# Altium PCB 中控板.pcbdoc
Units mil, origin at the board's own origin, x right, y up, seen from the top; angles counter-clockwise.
Board outline 4940 x 2875 mil, 2 copper layers (Top Layer, Bottom Layer); 77 components, 85 nets, 341 pads, 107 vias.
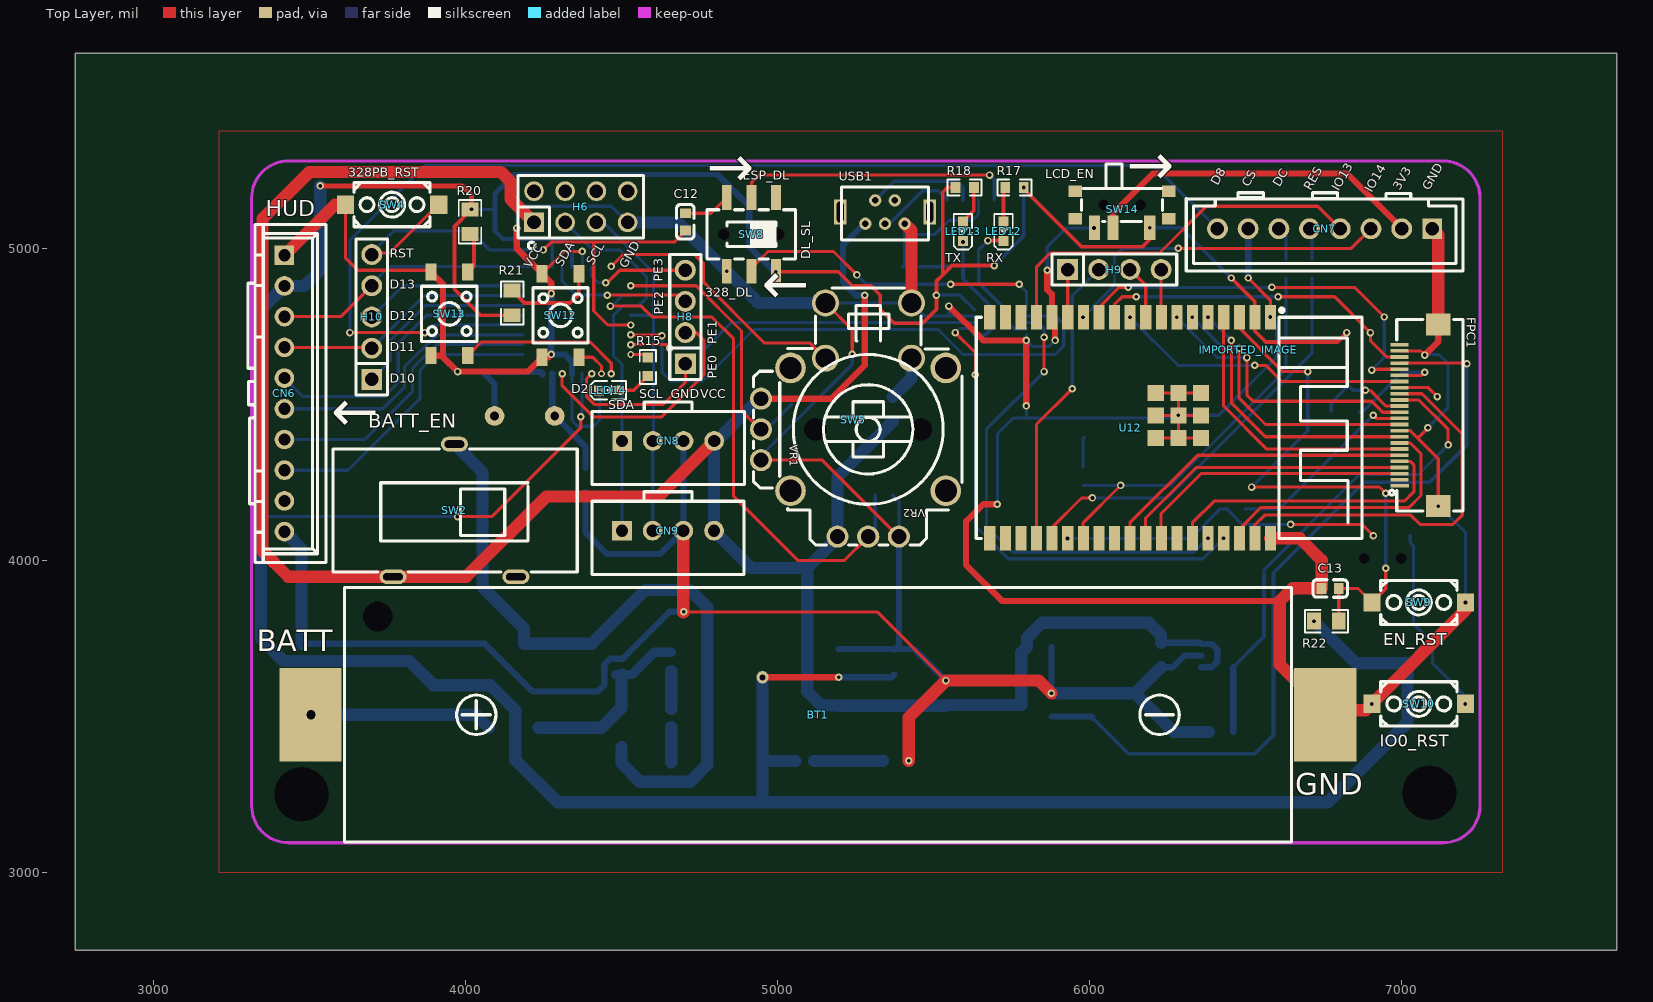
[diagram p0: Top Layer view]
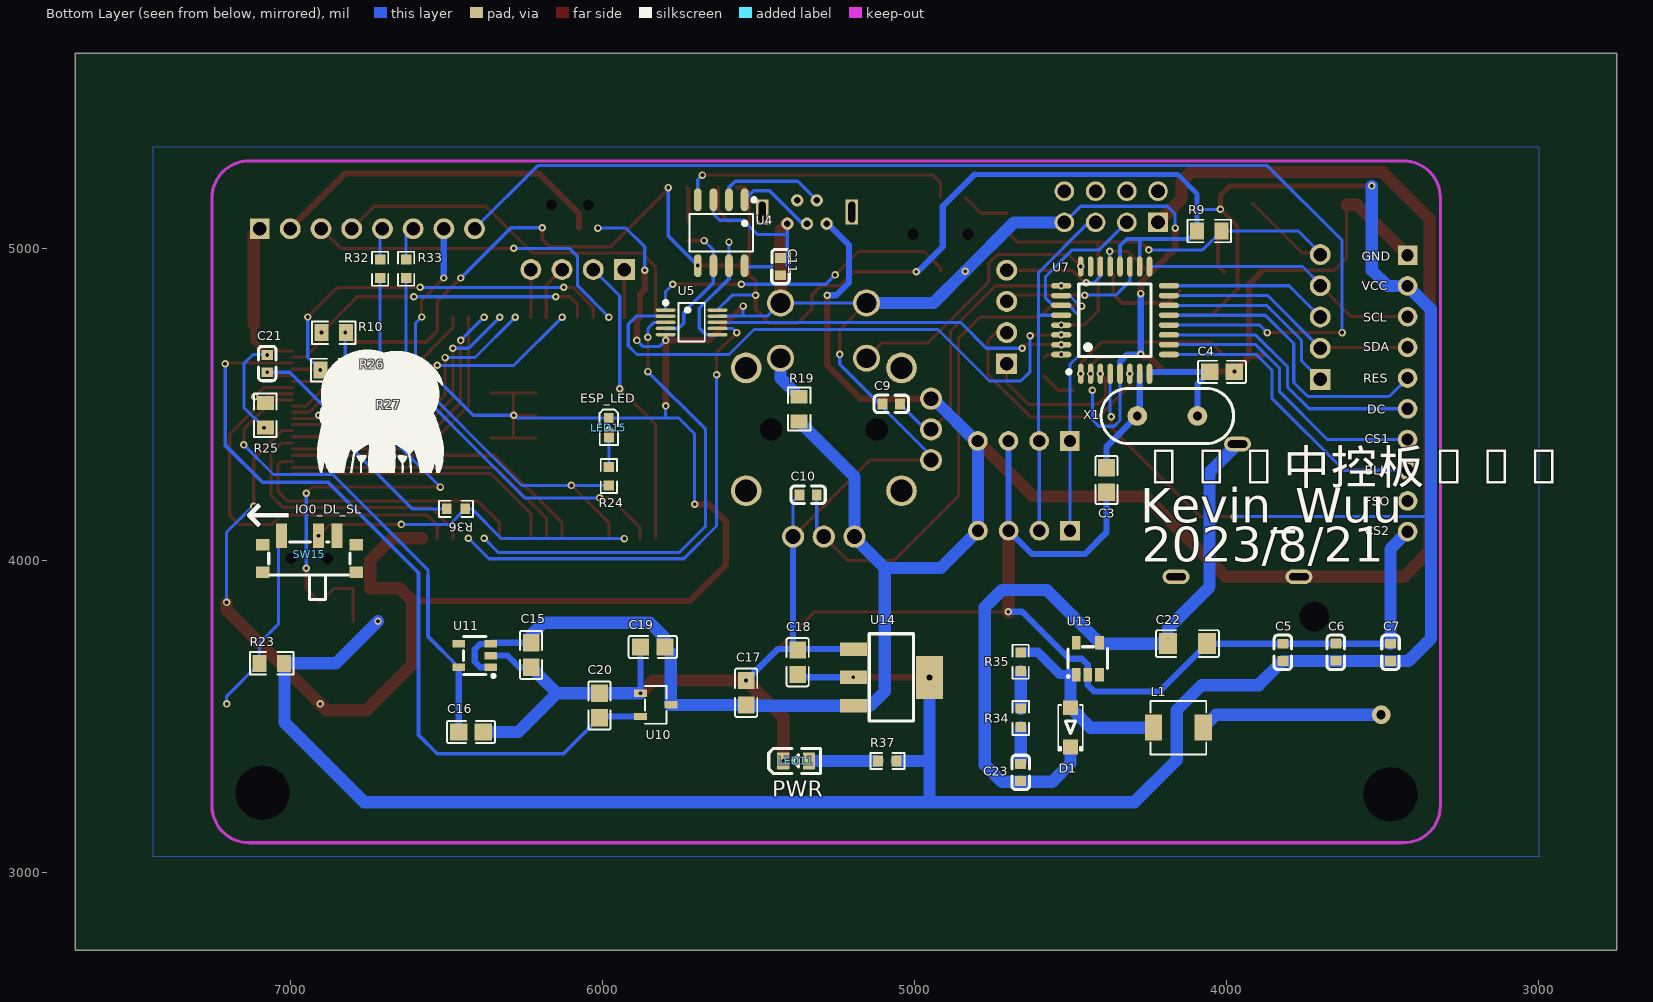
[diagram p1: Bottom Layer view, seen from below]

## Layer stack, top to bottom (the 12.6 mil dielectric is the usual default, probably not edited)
Top Layer: signal copper (thickness not stored)
Dielectric: dielectric 12.6, FR-4, Dk 4.8
Bottom Layer: signal copper (thickness not stored)

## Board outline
7690,2750 2750,2750 2750,5625 7690,5625
cut-out: 7176.61,3255 ccw(c7090,3255) 7003.39,3255 ccw(c7090,3255)
cut-out: 3561.61,3250 ccw(c3475,3250) 3388.39,3250 ccw(c3475,3250)

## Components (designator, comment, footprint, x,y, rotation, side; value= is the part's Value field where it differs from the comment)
BT1 "BH-18650-B1BA002" BATTERY-SMD_18650-1S-L77.1-W20.7-1 5130,3505 r90 top
C3 "0805CG220F500NT" C0805 4385,4257.35 r90 bottom
C4 "0805CG220F500NT" C0805 4015,4604.09 r0 bottom
C5 "CC0603KRX7R9BB104" C0603 3820,3705 r270 bottom
C6 "CC0603KRX7R9BB104" C0603 3650,3705.61 r90 bottom
C7 "CC0603KRX7R9BB104" C0603 3475,3705 r270 bottom
C9 "GRM188R61E106KA73D" C0603 5075,4501.55 r0 bottom
C10 "GRM188R61E106KA73D" C0603 5341.15,4210 r180 bottom
C11 "CC0603KRX7R9BB104" C0603 5430,4941.31 r270 bottom
C12 "CC0603KRX7R9BB104" C0603 4704.89,5085 r270 top
C13 "CC0603KRX7R9BB104" C0603 6771.73,3910 r180 top
C15 "CL21B105KBFNNNE" C0805 6229.37,3696.74 r90 bottom
C16 "CL21B105KBFNNNE" C0805 6421.81,3450 r0 bottom
C17 "CL21B105KBFNNNE" C0805 5540.16,3575.51 r90 bottom
C18 "CL21B105KBFNNNE" C0805 5375.09,3673.46 r90 bottom
C19 "CL21B105KBFNNNE" C0805 5839.26,3722.21 r0 bottom
C20 "CL21B105KBFNNNE" C0805 6010,3534.86 r90 bottom
C21 "CC0603KRX7R9BB104" C0603 7075,4630.56 r270 bottom
C22 "CL31A226KAHNNNE" C1206 4125.57,3733.11 r0 bottom
C23 "CC0603JRNPO9BN121" C0603 4660.11,3320 r270 bottom
CN6 "HC-XHB-10A" CONN-TH_10P-P2.50_HCTL_HC-XHB-10A 3420,4535 r270 top
CN7 "HC-XHB-8A" CONN-TH_8P-P2.50_HCTL_HC-XHB-8A 6755,5062.71 r180 top
CN8 "HX25035-4A" CONN-TH_4P-P2.50_HX25035-4A 4650,4382.78 r0 top
CN9 "HX25035-4A" CONN-TH_4P-P2.50_HX25035-4A 4649.46,4095 r0 top
D1 "MSK240AW" SOD-123FL_L2.8-W1.8-LS3.7-RD 4500.55,3465 r90 bottom
FPC1 "AFC24-S24FIA-00" FPC-SMD_P0.50-24P_QCHF-SM-H2.0 7056.18,4465 r270 top
H6 "DS1023-2*4SF11" HDR-TH_8P-P2.54-V-F-R2-C4-S2.54-1 4370,5133.14 r0 top
H8 "PZ254V-11-04P" HDR-TH_4P-P2.54-V-M 4705,4780 r90 top
H9 "PZ254V-11-04P" HDR-TH_4P-P2.54-V-M 6080,4932.15 r0 top
H10 "HDR-M_2.54_1x5P" HDR-TH_5P-P2.54-V-M 3700,4780 r90 top
IMPORTED_IMAGE "IMPORTED_IMAGE" IMPORTED_IMAGE 6510,4675 r0 top
L1 "MWSA0402S-2R2MT" IND-SMD_L4.4-W4.2 4155,3463.67 r180 bottom
LED11 "NCD0805B2" LED0805-R-RD 5380,3357.38 r180 bottom
LED12 "NCD0603R5" LED0603-RD 5725,5055 r90 top
LED13 "NCD0603R5" LED0603-RD 5595,5055 r90 top
LED14 "NCD0603R5" LED0603-RD 4460,4545 r0 top
LED15 "NCD0603R5" LED0603-RD 5980.21,4425 r270 bottom
R9 "RMCF0805FT10K0" R0805 4055.65,5055.63 r0 bottom
R10 "0805W8F4701T5E" R0805 6861.67,4730 r180 bottom
R15 "0603WAF4700T5E" R0603 4585,4620 r90 top
R17 "0603WAF4700T5E" R0603 5760,5195 r0 top
R18 "0603WAF4700T5E" R0603 5600,5195 r180 top
R19 "RMCF0805FT10K0" R0805 5370,4485 r270 bottom
R20 "RMCF0805FT10K0" R0805 4015,5085.31 r90 top
R21 "RMCF0805FT10K0" R0805 4150,4825 r270 top
R22 "RMCF0805FT10K0" R0805 6759.92,3805 r180 top
R23 "RMCF0805FT10K0" R0805 7060.62,3670 r180 bottom
R24 "0603WAF4700T5E" R0603 5980,4269.89 r270 bottom
R25 "RMCF0805FT10K0" R0805 7080.94,4465 r90 bottom
R26 "0805W8F4701T5E" R0805 6865,4609.94 r180 bottom
R27 "RMCF0805FT10K0" R0805 6814.69,4480 r180 bottom
R32 "0603WAF0000T5E" R0603 6713.34,4934.68 r270 bottom
R33 "0603WAF0000T5E" R0603 6630,4934.68 r270 bottom
R34 "RC0603FR-073RL" R0603 4660,3495 r270 bottom
R35 "0603WAF200KT5E" R0603 4660.11,3675 r270 bottom
R36 "0603WAF0000T5E" R0603 6470,4165 r0 bottom
R37 "0603WAF4700T5E" R0603 5087.52,3356.83 r180 bottom
SW2 "SS12J01 071" SW-TH_SHOU-HAN_SS12J01 3965,4160 r180 top
SW4 "K2-1107ST-A4DW-06_C118141" KEY-SMD_L6.2-W3.6-LS8.0 3765,5140 r180 top
SW5 "RKJXV1224005" SW-TH_RKJXV1224005 5243.81,4450.56 r180 top
SW8 "MS-22D28-G020" SW-SMD_MS-22D28-G020 4916.73,5045 r0 top
SW9 "K2-1107ST-A4DW-06_C118141" KEY-SMD_L6.2-W3.6-LS8.0 7055.82,3865 r0 top
SW10 "K2-1107ST-A4DW-06_C118141" KEY-SMD_L6.2-W3.6-LS8.0 7055.82,3540 r180 top
SW12 "TS-1009S-03826" SW-SMD_4P-L4.5-W4.5-P3.00-LS7.0 4304.81,4785 r270 top
SW13 "TS-1009S-03826" SW-SMD_4P-L4.5-W4.5-P3.00-LS7.0 3948.57,4790 r270 top
SW14 "MK-12C02-G020" SW-SMD_MK-12C02-G020 6105,5125 r180 top
SW15 "MK-12C02-G020" SW-SMD_MK-12C02-G020 6940.05,4020 r180 bottom
U4 "CH340N" SOP-8_L4.9-W3.9-P1.27-LS6.0-BL 5620,5050 r0 bottom
U5 "MSUSB30" MSOP-10_L3.0-W3.0-P0.50-LS5.0-BL 5715,4762.96 r270 bottom
U7 "ATMEGA328PB-AU" TQFP-32_L7.0-W7.0-P0.80-LS9.0-BL 4357.52,4770 r180 bottom
U10 "XC6206-2.8V" SOT-23-3_L2.9-W1.6-P1.90-LS2.8-BR 5830,3536.83 r0 bottom
U11 "RT9013-12GB" SOT-23-5_L3.0-W1.7-P0.95-LS2.8-BR 6410,3694.77 r180 bottom
U12 "ESP32-WROVER-E-N4R8" WIFI-SMD_ESP32-WROVER-E 6130.74,4425 r270 top
U13 "TPS613222ADBVR" TSOT-23-5_L2.9-W1.6-P0.95-LS2.8-BR 4445,3685.07 r270 bottom
U14 "TLV1117LV33DCYR" SOT-223_L6.7-W3.5-P2.30-BR 5074.69,3625 r0 bottom
USB1 "920-462A2021Y10102" MINI-USB-TH_C13453 5345,5116.48 r0 top
X1 "X49SD8MSD2SC" OSC-TH_L10.0-W4.5-P5.00 4190,4462.84 r90 bottom

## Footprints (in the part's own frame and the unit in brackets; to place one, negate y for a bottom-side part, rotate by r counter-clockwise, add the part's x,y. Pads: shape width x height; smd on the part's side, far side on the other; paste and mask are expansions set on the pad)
BATTERY-SMD_18650-1S-L77.1-W20.7-1 [mil]
  rect 300x200 smd mask+2.01: 1(0,-1626.5) 2(0,1626.5)
  Multi-Layer board cut-out: 314.96,1363.78 335.46,1368.45 351.9,1381.56 361.02,1400.51 361.02,1421.53 351.9,1440.48 335.46,1453.59 314.96,1458.26 314.96,1458.26 294.46,1453.59 278.02,1440.48 268.9,1421.53 268.9,1400.51 278.02,1381.56 294.46,1368.45 314.96,1363.78
  silkscreen extent -408,-1518 408,1518
C0603 [mm]
  rect 0.8x0.9 smd mask+0.051: 1(-0.7,0) 2(0.7,0)
  silkscreen extent -1.41,-0.71 1.39,0.72
C0805 [mm]
  rect 1.41x1.35 smd paste-100 mask+0.051: 1(-1,0) 2(1,0)
  silkscreen extent -1.96,-0.9 1.96,0.9
C1206 [mm]
  rect 1.485x1.728 smd paste-100 mask+0.051: 1(-1.593,0) 2(1.593,0)
  silkscreen extent -2.56,-1.09 2.56,1.09
CONN-TH_4P-P2.50_HX25035-4A [mm]
  rect 1.6x1.6 hole 1 mask+0.051: 1(-3.75,0)
  round 1.6 hole 1 mask+0.051: 2(-1.25,0) 3(1.25,0) 4(3.75,0)
  silkscreen extent -6.2,-3.55 6.2,3.17
CONN-TH_8P-P2.50_HCTL_HC-XHB-8A [mm]
  rect 1.6x1.7 hole 1.1 mask+0.051: 1(-8.75,0)
  round 1.7 hole 1.1 mask+0.051: 2(-6.25,0) 3(-3.75,0) 4(-1.25,0) 5(1.25,0) 6(3.75,0) 7(6.25,0)
  round 1.7 hole 1.1 paste+0 mask+0.05: 8(8.75,0)
  silkscreen extent -11.25,-2.94 11.29,3.43
CONN-TH_10P-P2.50_HCTL_HC-XHB-10A [mm]
  rect 1.6x1.6 hole 1 mask+0.051: 1(-11.25,0)
  round 1.6 hole 1 mask+0.051: 2(-8.75,0) 3(-6.25,0) 4(-3.75,0) 5(-1.25,0) 6(1.25,0) 7(3.75,0) 8(6.25,0) 9(8.75,0) 10(11.25,0)
  silkscreen extent -13.75,-2.96 13.75,3.4
FPC-SMD_P0.50-24P_QCHF-SM-H2.0 [mm]
  rect 0.3x1.5 smd mask+0.051: 1(5.75,-1.574) 2(5.252,-1.576) 3(4.752,-1.576) 4(4.252,-1.576) 5(3.752,-1.576) 6(3.252,-1.576) 7(2.752,-1.576) 8(2.252,-1.576) 9(1.752,-1.576) 10(1.252,-1.576) 11(0.752,-1.576) 12(0.252,-1.576) 13(-0.248,-1.576) 14(-0.748,-1.576) 15(-1.248,-1.576) 16(-1.748,-1.576) 17(-2.248,-1.576) 18(-2.748,-1.576) 19(-3.248,-1.576) 20(-3.748,-1.576) 21(-4.248,-1.576) 22(-4.748,-1.576) 23(-5.248,-1.576) 24(-5.748,-1.576)
  rect 1.8x2 smd mask+0.051: 25(7.4,1.576) 26(-7.4,1.576)
  silkscreen extent -7.8,-2.4 7.8,3.6
HDR-TH_4P-P2.54-V-M [mm]
  rect 1.7x1.7 hole 1.1 mask+0.051: 1(-3.81,0)
  round 1.7 hole 1.1 mask+0.051: 2(-1.27,0) 3(1.27,0) 4(3.81,0)
  silkscreen extent -5.08,-1.27 5.08,1.27
HDR-TH_5P-P2.54-V-M [mm]
  rect 1.7x1.7 hole 1.1 mask+0.051: 1(-5.08,0)
  round 1.7 hole 1.1 mask+0.051: 2(-2.54,0) 3(0,0) 4(2.54,0) 5(5.08,0)
  silkscreen extent -6.35,-1.27 6.35,1.27
HDR-TH_8P-P2.54-V-F-R2-C4-S2.54-1 [mm]
  rect 1.6x1.6 hole 1.1 mask+0.051: 1(-3.81,-1.27)
  round 1.6 hole 1.1 mask+0.051: 2(-3.81,1.27) 3(-1.27,-1.27) 4(-1.27,1.27) 5(1.27,-1.27) 6(1.27,1.27) 7(3.81,-1.27) 8(3.81,1.27)
  silkscreen extent -5.1,-3.42 5.1,2.55
IMPORTED_IMAGE [mil]
IND-SMD_L4.4-W4.2 [mm]
  rect 1.4x2.12 smd mask+0.051: 1(2.028,0) 2(-2.028,0)
  silkscreen extent -2.28,-2.18 2.28,2.18
KEY-SMD_L6.2-W3.6-LS8.0 [mm]
  rect 1.4x1.5 smd mask+0.051: 1(-3.8,0) 2(3.8,0)
  silkscreen extent -3.1,-1.8 3.1,1.8
LED0603-RD [mm]
  rect 0.8x0.8 smd mask+0.051: 1(-0.799,-0.003) 2(0.799,0.003)
  silkscreen extent -1.49,-0.75 1.39,0.76
LED0805-R-RD [mm]
  rect 1x1.4 smd mask+0.051: 1(1.05,0) 2(-1.05,0)
  silkscreen extent -2.22,-1.04 1.99,1.01
MINI-USB-TH_C13453 [mm]
  round 1 hole 0.55 mask+0.051: 1(-1.6,-0.95) 2(-0.8,0.95) 3(0,-0.95) 4(0.8,0.95) 5(1.6,-0.95)
  rect 1x2 hole 0.55 slot 1.7 at 90 deg mask+0.051: 6(3.65,0) 7(-3.65,0)
  silkscreen extent -3.56,-2.29 3.56,2.03
MSOP-10_L3.0-W3.0-P0.50-LS5.0-BL [mm]
  oval 0.28x1.62 smd mask+0.051: 1(-1,-2.11) 2(-0.5,-2.11) 3(0,-2.11) 4(0.5,-2.11) 5(1,-2.11) 6(1,2.11) 7(0.5,2.11) 8(0,2.11) 9(-0.5,2.11) 10(-1,2.11)
  silkscreen extent -1.74,-2.26 1.58,1.07
OSC-TH_L10.0-W4.5-P5.00 [mm]
  round 1.6 hole 0.7 mask+0.051: 1(0,2.45) 2(0,-2.45)
  silkscreen extent -2.25,-5.39 2.25,5.39
R0603 [mil]
  rect 31.75x34.02 smd paste-3937.01 mask+2: 1(-29.66,0) 2(29.66,0)
  silkscreen extent -55,-26 55,26
R0805 [mm]
  rect 1.133x1.377 smd paste-100 mask+0.051: 1(-1,0) 2(1,0)
  silkscreen extent -1.76,-0.92 1.76,0.92
SOD-123FL_L2.8-W1.8-LS3.7-RD [mm]
  rect 1.2x1.2 smd mask+0.051: 1(-1.6,0) 2(1.6,0)
  silkscreen extent -1.9,-1 1.8,1
SOP-8_L4.9-W3.9-P1.27-LS6.0-BL [mm]
  oval 0.63x1.865 smd mask+0.051: 1(-1.905,-2.682) 2(-0.635,-2.682) 3(0.635,-2.682) 4(1.905,-2.682) 5(1.905,2.682) 6(0.635,2.682) 7(-0.635,2.682) 8(-1.905,2.682)
  silkscreen extent -2.82,-2.83 2.58,1.52
SOT-23-3_L2.9-W1.6-P1.90-LS2.8-BR [mm]
  rect 1.07x0.6 smd mask+0.051: 1(1.235,-0.95) 2(1.235,0.95) 3(-1.235,0)
  silkscreen extent -0.88,-1.54 0.88,1.54
SOT-23-5_L3.0-W1.7-P0.95-LS2.8-BR [mm]
  rect 1x0.6 smd mask+0.051: 1(1.3,-0.95) 2(1.3,0) 3(1.3,0.95) 4(-1.3,0.95) 5(-1.3,-0.95)
  silkscreen extent -0.9,-1.78 1.65,1.55
SOT-223_L6.7-W3.5-P2.30-BR [mm]
  rect 2.2x1.1 smd mask+0.051: 1(3.099,-2.3) 2(3.099,0) 3(3.099,2.3)
  rect 2.2x3.5 smd mask+0.051: 4(-3.099,0)
  silkscreen extent -1.8,-3.55 1.8,3.55
SW-SMD_4P-L4.5-W4.5-P3.00-LS7.0 [mm]
  rect 1.4x0.9 smd mask+0.051: 1(-3.4,1.5) 2(3.4,1.5) 3(-3.4,-1.5) 4(3.4,-1.5)
  silkscreen extent -2.25,-2.25 2.25,2.25
SW-SMD_MK-12C02-G020 [mm]
  rect 0.9x2 smd mask+0.051: 1(-2.25,1.491) 2(0.75,1.491) 3(2.25,1.491)
  rect 1.1x0.93 smd mask+0.051: 4(3.8,0.779) 5(3.8,-1.491) 6(-3.8,-1.491) 7(-3.8,0.779)
  Multi-Layer board cut-out: 1.075,-0.356 1.117,-0.54 1.235,-0.688 1.405,-0.77 1.595,-0.77 1.765,-0.688 1.883,-0.54 1.925,-0.356 1.925,-0.356 1.883,-0.171 1.765,-0.023 1.595,0.059 1.405,0.059 1.235,-0.023 1.117,-0.171 1.075,-0.356
  Multi-Layer board cut-out: -1.925,-0.356 -1.883,-0.54 -1.765,-0.688 -1.595,-0.77 -1.405,-0.77 -1.235,-0.688 -1.117,-0.54 -1.075,-0.356 -1.075,-0.356 -1.117,-0.171 -1.235,-0.023 -1.405,0.059 -1.595,0.059 -1.765,-0.023 -1.883,-0.171 -1.925,-0.356
  silkscreen extent -3.3,-3.71 3.3,0.99
SW-SMD_MS-22D28-G020 [mm]
  rect 0.8x2 smd mask+0.051: 1(-2,3) 2(0,3) 3(2,3) 4(-2,-3) 5(0,-3) 6(2,-3)
  Multi-Layer board cut-out: -1.8,0 -1.844,0.195 -1.969,0.352 -2.15,0.439 -2.35,0.439 -2.531,0.352 -2.655,0.195 -2.7,0 -2.7,0 -2.655,-0.195 -2.531,-0.352 -2.35,-0.439 -2.15,-0.439 -1.969,-0.352 -1.844,-0.195 -1.8,0
  Multi-Layer board cut-out: 2.7,0 2.655,0.195 2.531,0.352 2.35,0.439 2.15,0.439 1.969,0.352 1.844,0.195 1.8,0 1.8,0 1.844,-0.195 1.969,-0.352 2.15,-0.439 2.35,-0.439 2.531,-0.352 2.655,-0.195 2.7,0
  silkscreen extent -3.6,-2 3.6,2
SW-TH_RKJXV1224005 [mm]
  round 1.8 hole 1.2 mask+0.051: 1(7.527,-1.719) 2(7.527,0.781) 3(7.527,3.281) 4(1.297,9.511) 5(-1.202,9.511) 6(-3.703,9.511)
  round 2.5 hole 1.8 mask+0.051: 7(-7.527,5.781) 8(-7.527,-4.219) 9(5.123,-4.219) 10(5.123,5.781)
  round 2.2 hole 1.6 mask+0.051: a(-4.722,-5.011) b(-4.722,-9.511) c(2.278,-5.011) d(2.278,-9.511)
  Multi-Layer board cut-out: -6.403,0.781 -6.314,0.39 -6.064,0.077 -5.703,-0.097 -5.302,-0.097 -4.942,0.077 -4.692,0.39 -4.603,0.781 -4.603,0.781 -4.692,1.171 -4.942,1.485 -5.302,1.658 -5.703,1.658 -6.064,1.485 -6.314,1.171 -6.403,0.781
  Multi-Layer board cut-out: 2.197,0.781 2.286,0.39 2.536,0.077 2.897,-0.097 3.298,-0.097 3.658,0.077 3.908,0.39 3.997,0.781 3.997,0.781 3.908,1.171 3.658,1.485 3.298,1.658 2.897,1.658 2.536,1.485 2.286,1.171 2.197,0.781
  silkscreen extent -8.85,-10.72 8.15,10.2
SW-TH_SHOU-HAN_SS12J01 [mm]
  oval 2.2x1.2 hole 0.6 slot 1.6 at 0 deg paste+0 mask+0.05: 1(-5,5.4) 2(0,-5.4) 3(5,5.4)
  silkscreen extent -10,-5 9.9,5
TQFP-32_L7.0-W7.0-P0.80-LS9.0-BL [mm]
  oval 0.45x1.65 smd mask+0.051: 1(-2.8,-4.369) 2(-2,-4.369) 3(-1.2,-4.369) 4(-0.4,-4.369) 5(0.4,-4.369) 6(1.2,-4.369) 7(2,-4.369) 8(2.8,-4.369) 17(2.8,4.369) 18(2,4.369) 19(1.2,4.369) 20(0.4,4.369) 21(-0.4,4.369) 22(-1.2,4.369) 23(-2,4.369) 24(-2.8,4.369)
  oval 1.65x0.45 smd mask+0.051: 9(4.381,-2.8) 10(4.381,-2) 11(4.381,-1.2) 12(4.381,-0.4) 13(4.381,0.4) 14(4.381,1.2) 15(4.381,2) 16(4.381,2.8) 25(-4.381,2.8) 26(-4.381,2) 27(-4.381,1.2) 28(-4.381,0.4) 29(-4.381,-0.4) 30(-4.381,-1.2) 31(-4.381,-2) 32(-4.381,-2.8)
  silkscreen extent -3.91,-4.36 2.94,2.95
TSOT-23-5_L2.9-W1.6-P0.95-LS2.8-BR [mm]
  rect 1.1x0.7 smd mask+0.051: 1(1.294,-0.951) 2(1.294,-0.001) 3(1.294,0.951) 4(-1.294,0.951) 5(-1.294,-0.949)
  silkscreen extent -0.97,-1.65 1.52,1.61
WIFI-SMD_ESP32-WROVER-E [mm]
  rect 2x0.9 smd mask+0.051: 1(-9,11.43) 2(-9,10.16) 3(-9,8.89) 4(-9,7.62) 5(-9,6.35) 6(-9,5.08) 7(-9,3.81) 8(-9,2.54) 9(-9,1.27) 10(-9,0) 11(-9,-1.27) 12(-9,-2.54) 13(-9,-3.81) 14(-9,-5.08) 15(-9,-6.35) 16(-9,-7.62) 17(-9,-8.89) 18(-9,-10.16) 19(-9,-11.43) 20(9,-11.43) 21(9,-10.16) 22(9,-8.89) 23(9,-7.62) 24(9,-6.35) 25(9,-5.08) 26(9,-3.81) 27(9,-2.54) 28(9,-1.27) 29(9,0) 30(9,1.27) 31(9,2.54) 32(9,3.81) 33(9,5.08) 34(9,6.35) 35(9,7.62) 36(9,8.89) 37(9,10.16) 38(9,11.43)
  rect 1.33x1.33 smd mask+0.051: 39(-2.835,5.765) 39(-2.835,3.93) 39(-2.835,2.095) 39(-1,5.765) 39(-1,3.93) 39(-1,2.095) 39(0.835,3.93) 39(0.835,2.095) 39(0.835,5.765)
  silkscreen extent -9.72,-12.53 9,18.87

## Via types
v1: diameter 24.02, hole 12.01, Top Layer to Bottom Layer, 100 vias
v2: diameter 21.65, hole 12.01, Top Layer to Bottom Layer, 2 vias
v3: diameter 23.62, hole 12.01, Top Layer to Bottom Layer, 2 vias
v4: diameter 23.23, hole 12.01, Top Layer to Bottom Layer, 1 vias
v5: diameter 59.06, hole 29.53, Top Layer to Bottom Layer, 1 vias
v6: diameter 39.37, hole 19.68, Top Layer to Bottom Layer, 1 vias

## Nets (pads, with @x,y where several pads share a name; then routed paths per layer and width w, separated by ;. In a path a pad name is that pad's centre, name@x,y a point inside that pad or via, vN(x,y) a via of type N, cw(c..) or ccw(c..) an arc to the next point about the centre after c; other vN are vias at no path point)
2.4LCD_DC: CN7.6 R33.1 | length 107.7
  Bottom Layer w10: CN7.6 6630,5040.08 R33.1
2.4LCD_RES: CN7.5 R32.1 | length 101.5
  Bottom Layer w10: CN7.5 6713.34,5055.15 R32.1
$1N4382: LED11.1 R37.1 | length 221.7
  Bottom Layer w39.37: R37.1 5338.1,3356.83 LED11.1
$1N6601: LED14.2 R15.1 | length 112.2
  Top Layer w10: LED14.2 4539.8,4545.14 R15.1
$1N6970: LED12.2 R17.1 | length 110.8
  Top Layer w11.81: LED12.2 5724.86,5189.52 R17.1
$1N6973: LED13.2 R18.1 | length 122.9
  Top Layer w11.81: LED13.2 5629.66,5121.27 R18.1
$1N8671: R19.1 SW5.a | length 148.2
  Bottom Layer w39.37: R19.1 5429.7,4584.07 SW5.a
$1N9237: R21.1 SW12.1 | length 307.1
  Top Layer w11.81: R21.1 4189.37,4825 4335,4825 4363.87,4853.87 SW12.1
$1N9240: R20.1 SW13.1 | length 114.2
  Top Layer w11.81: SW13.1 4027.63,4943.86 R20.1@4027.63,5029.8
$1N10624: C11.1 U4.8 | length 88.7
  Bottom Layer w11.81: 5457.56,4941.31 5541.92,4941.31 U4.8
$1N11026: C12.1 SW8.1 | length 154
  Top Layer w10: C12.1 4787.44,5112.56 SW8.1
$1N11882: LED15.2 R24.1 | length 95.5
  Bottom Layer w10: R24.1 5980,4389.93 LED15.2@5983.6,4393.52
$1N55474: R34.1 R35.2 | length 120.7
  Bottom Layer w39.37: R34.1 4660.11,3524.77 R35.2
$1N55477: C23.1 R34.2 | length 112.8
  Bottom Layer w39.37: R34.2 4660.11,3465.23 C23.1@4660.11,3352.56
$1N55562: D1.2 L1.2 R35.1 U13.1 | length 606.2
  Bottom Layer w30: U13.1 4501.8,3634.12 4534.12,3634.12 4605,3705 4659.77,3705 R35.1
  Bottom Layer w39.37: L1.2 4436.23,3463.67 D1.2 4500.55,3632.87 4501.8,3634.12
$1N55674: R23.1 SW10.1 SW15.1 | length 611.7
  Bottom Layer w10: SW15.1 7028.63,4057.04 7038.63,4047.04 7038.63,3796.37 7100,3735 R23.1 7205,3564.99 v1(7205,3540)
$1N55884: FPC1.12 R36.2 | length 622.9
  Top Layer w10: v1(6910,4465) 6919.92,4455.08 FPC1.12
  Bottom Layer w10: R36.2 6610,4165 v1(6910,4465)
A1: SW5.c U7.24 | length 874.8
  Top Layer w10: v1(4467.76,4942) 4505.76,4980 4735,4980 4762.5,4952.5 4762.5,4892.5 4958.85,4696.15 5105.81,4696.15 SW5.c
A2: C9.1 SW5.2 U7.25 | length 891.4
  Top Layer w10: v1(4530.02,4880.24) 4739.76,4880.24 4885,4735 4885,4480 4945.18,4419.82 SW5.2
  Bottom Layer w10: SW5.2 4965.71,4419.82 C9.1
A3: C10.2 SW5.5 U7.26 | length 1713.2
  Top Layer w10: v1(4465,4815) 4563.76,4815 4598.76,4780 4790,4780 4860,4710 4860,4205 5065,4000 5215,4000 SW5.5@5291.12,4076.12
  Bottom Layer w10: v1(4465,4815) 4470,4815 4503.74,4848.74 U7.26 ; SW5.5 5313.59,4098.55 C10.2
A4: CN8.1 CN9.1 H6.3 U7.27 | length 1231.5
  Bottom Layer w10: H6.3 4408.14,4995 4495,4995 4580,4910 4580,4840 4557.24,4817.24 U7.27 4506.41,4817.24 4475,4785.84 4475,4655 4502.36,4627.64 CN8.1 4502.36,4095.54 CN9.1
A5: CN8.2 CN9.2 H6.5 U7.28 | length 1151.4
  Bottom Layer w10: H6.5 4441.86,5083.14 4602.99,4922.01 4602.99,4785.19 4602.43,4785.75 ; U7.28 4602.43,4785.75 ; CN9.2 4600.79,4095.54 CN8.2 4602.43,4384.42 4602.43,4785.75
ADC1_P36: FPC1.7 U12.4 | length 905.8
  Top Layer w10: U12.4@6430,4779.33 6430,4495 6568.34,4356.66 FPC1.7
ADC1_P39: FPC1.9 U12.5 | length 890.1
  Top Layer w10: v1(6455,4705) 6455,4505 6563.97,4396.03 FPC1.9
  Bottom Layer w10: v1(6380,4779.33) 6380.67,4779.33 v1(6455,4705)
BATT: C22.2 C23.2 D1.1 SW2.2 U13.4 | length 2294.1
  Bottom Layer w39.37: SW2.2 4055,4282.6 4055,3915 4188.27,3781.73 C22.2 4404.66,3733.11 U13.4 4576.55,3905 4720,3905 4775,3850 4775,3345 4720,3290 4662.55,3290 C23.2 4657.67,3290 4560,3290 4500.55,3349.45 D1.1
BATT_AS: C15.2 C17.1 C19.1 CN8.4 CN9.4 H6.1 R19.2 SW2.3 SW5.1 SW5.4 U10.3 U11.1 U11.3 U14.3 USB1.1 | length 8190.1
  Top Layer w20: SW5.1 5173.25,4518.25 5280,4625 v1(5280,4850)
  Top Layer w39.37: H6.1 4145,5158.14 4145,5213.81 4113.81,5245 3500,5245 3350,5095 3350,4030 3432.6,3947.4 SW2.3 4002.4,3947.4 4260,4205 4619.86,4205 CN8.4
  Bottom Layer w20: v1(5280,4850) 5251.72,4850 5210,4891.72 5210,5010 5279.08,5079.08 USB1.1 ; C15.2 6354.88,3736.11 U11.3 6392.83,3732.17 6410,3715 6410,3675 6392.37,3657.37 U11.1
  Bottom Layer w39.37: SW5.1 4940.35,4518.25 4797.1,4375 CN9.4 4916.26,3975.85 5095.85,3975.85 ; R19.2 5370,4445 5192.73,4267.73 SW5.4 5192.73,4072.73 5095.85,3975.85 ; C15.2 6229.37,3760.63 6190,3800 5848.42,3800 5799.89,3751.47 C19.1 5781.38,3703.7 U10.3 5780.69,3536.14 C17.1 5538.47,3534.45 U14.3 5196.15,3535 5140.47,3535 5095.85,3579.62 5095.85,3975.85
BATT_PRE: BT1.2 L1.1 | length 587.3
  Bottom Layer w39.37: v5(3505,3505) 4033.83,3505 L1.1
CH340N_RTS: SW8.2 U4.4 | length 906.1
  Top Layer w10: SW8.2 4916.73,5210 4941.73,5235 v1(5680,5235)
  Bottom Layer w10: v1(5680,5235) 5695,5220 U4.4
D0/RX0: U5.2 U7.30 | length 1829
  Top Layer w10: v4(4530.02,4722.76) 4627.24,4722.76 v1(4630,4720)
  Bottom Layer w10: v1(4630,4720) 4630,4605 4660,4575 4760,4575 4925,4740 5515,4740 5594.99,4660.01 5890.01,4660.01 5917.81,4687.81 5917.81,4757.19 5892.36,4782.64 U5.2
D1/TX0: U5.8 U7.31 | length 1140.9
  Top Layer w10: v3(4530.02,4691.26) 4643.74,4691.26 v1(4655,4680)
  Bottom Layer w10: v1(4655,4680) 4770,4680 4852.96,4762.96 U5.8
D2: R15.2 U7.32 | length 59.3
  Top Layer w10: v2(4530,4660) 4574.66,4660 R15.2
D3: SW13.2 U7.1 | length 540.6
  Top Layer w10: SW13.2 4051.49,4700 4400,4700 4467.76,4632.24 v1(4467.76,4598)
D4: SW12.2 U7.2 | length 108.9
  Top Layer w10: SW12.2 4407.9,4651.14 4436.26,4622.78 v2(4436.26,4598)
D5: CN6.8 U7.9 | length 971.3
  Bottom Layer w10: CN6.8 3623.93,4288.94 3855,4520 3855,4610 3904.76,4659.76 U7.9
D6: CN6.7 U7.10 | length 934.8
  Bottom Layer w10: CN6.7 3677.36,4387.35 3830,4540 3830,4615 3906.26,4691.26 U7.10
D7: CN6.6 U7.11 | length 901.3
  Bottom Layer w10: CN6.6 3735.78,4485.78 3805,4555 3805,4620 3907.76,4722.76 U7.11
D8: CN7.8 U7.12 | length 3823.8
  Top Layer w10: v1(3630,4730) v1(3870,4730)
  Bottom Layer w10: v1(3630,4730) 3630,5025 3870,5265 6208.22,5265 CN7.8 ; v1(3870,4730) 3894.25,4754.25 U7.12
D9: CN6.5 U7.13 | length 970.8
  Bottom Layer w10: CN6.5 3479.2,4525 3740,4525 3785,4570 3785,4695 3875.75,4785.75 U7.13
D10: H10.1 U7.14 | length 621.4
  Bottom Layer w10: H10.1 3760,4640 3760,4705 3872.24,4817.24 U7.14
D11: CN6.4 H10.2 U7.15 | length 835.9
  Top Layer w10: CN6.4 3697.64,4682.64 H10.2@3700,4685
  Bottom Layer w10: H10.2 3868.74,4848.74 U7.15
D12: H10.3 U7.16 | length 526.5
  Bottom Layer w10: H10.3 3800.24,4880.24 U7.16
D13: CN6.3 H10.4 U7.17 | length 896.9
  Top Layer w10: CN6.3 3601.07,4781.06 H10.4
  Bottom Layer w10: H10.4 3700,4885 3757,4942 U7.17
D+: U4.1 USB1.3 | length 256
  Bottom Layer w11.81: USB1.3 5359.08,5079.08 5465,5185 5515.61,5185 U4.1
D-: U4.2 USB1.2 | length 354.5
  Bottom Layer w11.81: USB1.2 5313.88,5153.88 5375,5215 5575,5215 5595,5195 U4.2
EN: C13.1 R22.1 SW9.1 U12.3 | length 1793.9
  Top Layer w10: U12.3@6480,4779.33 6480,4745 6620,4605 v1(6700,4605) ; v1(6520,4235) 6930,4235 v1(6950,4215) ; R22.1 C13.1 6861.22,3910 SW9.1 6950,3908.78 v1(6950,3975)
  Bottom Layer w10: v1(6520,4235) 6700,4415 v1(6700,4605) ; v1(6950,3975) v1(6950,4215)
ESP32_RXD: U5.3 U12.34 | length 1538.9
  Top Layer w10: v1(5855,4605) v1(5855,4715)
  Bottom Layer w10: U5.3 5834.96,4762.96 5855,4742.92 v1(5855,4715) ; v1(5855,4605) 5670,4420 5670,4110 5755,4025 6334.33,4025 v1(6380,4070.67)
ESP32_TXD: U5.7 U12.35 | length 1580
  Top Layer w10: v1(5570,4730) 5635,4665 v1(5635,4595)
  Bottom Layer w10: v1(5570,4730) 5583.27,4743.27 U5.7 ; v1(5635,4595) 5635,4110 5740,4005 6364.33,4005 v1(6430,4070.67)
GND: BT1.1 C3.1 C4.1 C5.1 C6.2 C7.1 C9.2 C10.1 C11.2 C13.2 C15.1 C16.1 C17.2 C18.2 C19.2 C20.2 C21.1 C22.1 CN6.1 CN6.10 CN7.1 CN7.7 CN8.3 CN9.3 FPC1.10 FPC1.23 FPC1.25 FPC1.26 H6.7 LED11.2 LED14.1 LED15.1 R25.1 SW4.2 SW5.3 SW5.6 SW5.b SW5.d SW8.4 SW9.2 SW10.2 SW12.3 SW12.4 SW13.3 SW13.4 SW14.3 U4.3 U5.5 U5.9 U7.5 U7.21 U10.1 U11.2 U12.1 U12.15 U12.38 U12.39 U13.2 U14.1 USB1.5 | length 20235
  Top Layer w10: SW4.2 3615.4,4969.6 3655,4930 3883.38,4930 SW13.3 ; SW12.3 4316.9,4990 v1(4375,4990) ; v1(4700,3835) 5320.05,3835 v1(5540.16,3614.88) ; SW5.3 5144.3,4321.4 SW5.6 ; SW5.d 5240,4739.12 v1(5240,4660) ; U12.39@6213.23,4392.14 U12.39@6285.47,4392.14 ; U12.39@6213.23,4464.36 U12.39@6285.47,4464.36 ; U12.39@6213.23,4536.61 U12.39@6285.47,4536.61 ; U12.39@6357.7,4392.14 U12.39@6285.47,4392.14 ; U12.39@6357.71,4464.36 U12.39@6285.47,4464.36 ; U12.39@6357.71,4536.61 U12.39@6285.47,4536.61 ; v1(6508.94,4905) 6580,4833.94 U12.1@6580,4779.33 ; C13.2 C13.2@6745,3910.83 ; FPC1.10 7028.68,4415.71 7052.93,4391.45 ; FPC1.23 7061.5,4671.62 v1(7075,4658.12) ; v1(7085,4425) 7085,4423.52 7052.93,4391.45 ; v1(7118.22,4173.66) 7118.22,4326.17 7052.93,4391.45 ; U12.39@6285.47,4392.14 U12.39@6285.47,4464.36 ; U12.39@6285.47,4464.36 U12.39@6285.47,4536.61
  Top Layer w20: SW13.4 3923.86,4656.14 3928.34,4651.66 ; SW13.3 3928.34,4885.03 3928.34,4651.66 ; v1(4165,5065) 4165,4999.62 SW12.3 4275,4889.62 v1(4275,4855) ; v1(4275,4660) 4266.14,4651.14 SW12.4 4199.62,4605 v1(3975,4605) 3928.34,4651.66 ; v1(5550,4815) 5660,4705 v1(5798.07,4705) v1(5798.07,4495) ; v1(5705,4180) 5660,4180 5605,4125 5605,3985 5720,3870 6610,3870 ; v1(5865,4930) 5865,4867.6 5880,4852.6 5880,4779.33 5890,4769.33 v1(5890,4705) ; v1(7075,4658.12) 7118.22,4701.34 FPC1.26
  Top Layer w39.37: CN6.1 3582.09,5140 SW4.2 ; v1@4698.68,3832.91 CN9.3 ; USB1.5 5429.7,5057.37 SW5.b ; v1(5421.35,3357.38) 5421.35,3496.07 v1(5540.16,3614.88) 5837.97,3614.88 v1(5878.62,3574.23) ; U12.38@6580,4070.67 6674.33,4070.67 6745,4000 6745,3910.83 6650.83,3910.83 6610,3870 6610,3666.5 6756.5,3520 6885,3520 v1(6905,3540) 7205.42,3840.42 v1(7205.42,3865) ; CN7.1 7118.22,5043.99 FPC1.26
  Bottom Layer w10: v1(4165,5065) 4165,5110 4190,5135 4468.14,5135 H6.7 ; U7.5 4341.77,4448.23 4360,4430 4410,4430 4430,4450 v1(4430,4545) ; U7.21 4375,4943.73 v1(4375,4990) ; SW5.3 4947.46,4335.54 5240,4628.07 v1(5240,4660) ; SW5.d SW5.b 5472.07,4782.64 5549.66,4782.64 ; C10.1 5389.58,4189.13 SW5.6 ; USB1.5@5397.44,5068.53 USB1.5 ; 5407.99,5044.83 5408.16,5045 5505,5045 5550,5090 5625,5090 5645,5110 U4.3 ; v1(5550,4815) 5550,4782.98 5549.66,4782.64 ; U5.9 5549.66,4782.64 ; v1(5705,4180) 5705,4405 5756.48,4456.48 5797.86,4456.48 ; v1(5798.07,4495) 5798.07,4456.68 5797.86,4456.48 ; U5.5 v1(5798.07,4705) 5818.07,4685 5870,4685 v1(5890,4705) ; v1(5865,4930) 5865,5005 5925,5065 v1(6015,5065) ; v1(6580,4780) 6600,4760 6600,4650 6415,4465 v1(6285,4465) 6276.48,4456.48 LED15.1 5797.86,4456.48 ; v1(7075,4658.12) 7076.88,4660 7120,4660 7150,4630 7150,4490 v1(7085,4425) ; v1(7118.22,4173.66) 7121.34,4173.66 7205.42,4089.58 v1(7205.42,3865)
  Bottom Layer w11.81: 5402.44,4941.31 5407.99,4946.86 5407.99,5044.83 USB1.5
  Bottom Layer w20: C7.1 C5.1 C22.1@4062.32,3732.56 ; v1(3975,4605) 3975,4604.72 C4.1 ; C22.1 C22.1@4062.32,3732.56 ; v1(4275,4855) v1(4275,4660) 4318.28,4660 4341.77,4636.51 U7.5 ; C3.1 4385,4090 4455,4020 4623.67,4020 CN9.3 4699.21,4095.54 CN8.3 ; v1(4700,3835) 4655,3835 4505,3685 4464.27,3685 4445.04,3665.78 U13.2 4445.04,3600 4425.04,3580 4214.88,3580 C22.1@4062.32,3732.56 ; U14.1 C18.2@5372.37,3715.55 ; C18.2 C18.2@5377.81,3715.55 ; SW5.6 5389.58,3727.33 C18.2@5377.81,3715.55 ; v1(5540.16,3614.88) 5439.5,3715.55 C18.2@5377.81,3715.55 ; v1(5878.62,3574.23) C19.2 ; C15.1 6267.37,3657.37 6304.77,3694.77 U11.2 ; v1(6508.94,4905) CN7.7
  Bottom Layer w39.37: CN6.10 3475,4037.09 C7.1 ; H6.7 4681.74,5083.14 v1(4837.99,4926.89) 4939.88,4825.01 SW5.d ; v1(5878.62,3574.23) C20.2 6146.23,3574.23 ; C15.1 6146.23,3574.23 ; C16.1 6270.46,3450 6146.23,3574.23
IO0: R36.1 SW15.2 U12.25 | length 1055.6
  Top Layer w10: v1(6645,4115) 6874.21,4115 v1(6910.52,4078.69)
  Bottom Layer w10: v1(5930,4070) 6324.46,4070 6419.46,4165 R36.1 6490.34,4115 v1(6645,4115)
IO2: R32.2 U12.24 | length 1340.6
  Top Layer w10: U12.24@5880,4070.67 5880,4105 5975,4200 v1(6010,4200)
  Bottom Layer w10: v1(6010,4200) 6250,4200 6713.34,4663.34 R32.2
IO4: R24.2 R33.2 U12.26 | length 1317.4
  Top Layer w10: U12.26@5980,4070.67 5980,4120 v1(6100,4240)
  Bottom Layer w10: R24.2 5980.23,4240 v1(6100,4240) 6260,4240 6630,4610 R33.2
IO5: FPC1.6 U12.29 | length 1003.3
  Top Layer w10: U12.29@6130,4070.67 6130,4120 6346.97,4336.97 FPC1.6
IO12: H9.1 U12.14 | length 153.1
  Top Layer w10: H9.1 5930.74,4931.41 U12.14
IO13: CN7.4 U12.16 | length 1245.6
  Top Layer w10: U12.16@5830,4779.33 5830,4940 5875,4985 6225,4985 6375,5135 6731.93,5135 CN7.4
IO14: CN7.3 U12.13 | length 1095
  Top Layer w10: v1(6285,5000) 6839.93,5000 CN7.3
  Bottom Layer w10: v1(5980,4779.33) 5980,4780 6080,4880 6080,4973.15 6106.85,5000 v1(6285,5000)
IO15: H9.2 U12.23 | length 944
  Top Layer w10: U12.23 5830.74,4435.74 v1(5945,4550)
  Bottom Layer w10: v1(5945,4550) 5945,4847.15 H9.2
IO18: FPC1.4 U12.30 | length 945.8
  Top Layer w10: U12.30@6180,4070.67 6180,4135 6342.6,4297.6 FPC1.4
IO19: FPC1.3 U12.31 | length 896.5
  Top Layer w10: U12.31@6230,4070.67 6230,4150 6357.92,4277.92 FPC1.3
IO21: FPC1.5 U12.33 | length 937.3
  Top Layer w10: U12.33@6330,4070.67 6330,4120 6400,4190 7010,4190 7040,4220 7040,4305.97 7028.68,4317.29 FPC1.5
IO22: FPC1.8 U12.36 | length 874.2
  Top Layer w10: U12.36@6480,4070.67 6480,4100 6550,4170 7025,4170 7063,4208 7063,4342.02 7028.68,4376.34 FPC1.8
IO23: FPC1.16 U12.37 | length 1259.9
  Top Layer w10: U12.37@6530,4070.67 6530,4113.37 6561.63,4145 7030,4145 7060,4115 7165,4115 7195,4145 7195,4405 7066.18,4533.82 FPC1.16
IO25: FPC1.18 U12.10 | length 949.5
  Top Layer w10: v1(6530,4625) 6565,4625 6616.81,4573.19 FPC1.18
  Bottom Layer w10: v1(6130,4779.33) 6284.33,4625 v1(6530,4625)
IO26: FPC1.22 R10.1 U12.11 | length 1060.4
  Top Layer w10: U12.11@6080,4779.33 6080,4820 6105,4845 v1(6150,4845) ; v1(6605,4845) 6786.04,4845 v1(6901.04,4730) 6901.04,4703.96 6953.07,4651.93 FPC1.22
  Bottom Layer w10: v1(6150,4845) v1(6605,4845)
IO27: FPC1.20 R26.1 U12.12 | length 1288.7
  Top Layer w10: U12.12@6030,4779.33 6030,4810 6095,4875 v1(6125,4875) ; v1(6585,4875) 6850,4875 v1(6945,4780) ; v1(6905,4610) 6907.53,4612.56 FPC1.20
  Bottom Layer w10: v1(6125,4875) v1(6585,4875) ; v1(6905,4610) 6945,4650 v1(6945,4780)
IO32: H9.4 U12.8 | length 153.1
  Top Layer w10: H9.4 6230,4780.07 U12.8
IO33: H9.3 U12.9 | length 173.8
  Top Layer w10: H9.3 6180.74,4881.41 U12.9
IO34: FPC1.11 U12.6 | length 900.3
  Top Layer w10: v1(6480,4680) 6480,4520 6564.6,4435.4 FPC1.11
  Bottom Layer w10: v1(6330,4779.33) 6429.33,4680 v1(6480,4680)
IO35: FPC1.13 U12.7 | length 910.6
  Top Layer w10: v1(6505,4650) 6505,4530 6525,4510 6905,4510 6940.23,4474.77 FPC1.13
  Bottom Layer w10: v1(6280,4779.33) 6409.33,4650 v1(6505,4650)
LCD_PWR: CN7.2 SW14.2 | length 1097.7
  Top Layer w19.68: SW14.2 6075.48,5110.68 6204.8,5240 6825,5240 7001.06,5063.94 CN7.2
MCU_RXD: LED12.1 U4.6 U5.4 | length 433.2
  Top Layer w11.81: v1(5675,5025) 5723.66,5025 LED12.1
  Bottom Layer w10: U4.6 5645,4995 v1(5675,5025)
  Bottom Layer w11.81: U4.6 5645,4890 5740,4795 5740,4760 5757.5,4742.5 5758.27,4743.27 U5.4
MCU_TXD: LED13.1 U4.7 U5.6 | length 381.3
  Bottom Layer w10: U4.7 v1(5595,5020)
  Bottom Layer w11.81: U4.7 5595,4902.68 5690,4807.68 5690,4745 5668.59,4723.59 U5.6
MSUSB30_SL: SW8.5 U5.1 | length 1025.9
  Top Layer w10: SW8.5 4916.73,4936.73 4970,4990 5180,4990 v1(5255,4915) ; v1(5555,4885) v1(5775,4885)
  Bottom Layer w10: v1(5255,4915) 5285,4885 v1(5555,4885) ; v1(5775,4885) 5798.07,4861.93 U5.1
PE0: H8.1 U7.3 | length 495.7
  Top Layer w10: v1(4404.76,4598) 4387.94,4581.18 4387.94,4525.59 4413.53,4500 4635,4500 4705,4570 H8.1@4705,4629.65
PE1: H8.2 U7.6 | length 770.4
  Top Layer w10: v1(4310.28,4598) 4310.28,4559.72 4410,4460 4630,4460 4765,4595 4765,4705 4740.35,4729.65 H8.2@4705,4729.65
PE2: H8.3 U7.19 | length 469
  Top Layer w10: v1(4455,4850) 4684.65,4850 H8.3@4705,4829.65
  Bottom Layer w10: U7.19 4310.28,4894.72 4355,4850 v1(4455,4850)
PE3: H8.4 U7.22 | length 356.8
  Top Layer w10: v1(4450,4890) 4455,4890 4494.65,4929.65 H8.4@4705,4929.65
  Bottom Layer w10: U7.22 4404.76,4910.24 4425,4890 v1(4450,4890)
PWDN: FPC1.17 R25.2 | length 132.7
  Top Layer w10: FPC1.17 7086.49,4553.51 v1(7115,4525)
RESET: C21.2 FPC1.19 R27.1 | length 348.1
  Top Layer w10: FPC1.19 7064.88,4592.88 v1(7075,4603)
  Bottom Layer w10: R27.1@6865,4475 6875,4475 7003,4603 v1(7075,4603)
RST: C12.2 H10.5 R9.1 SW4.1 U7.29 | length 1729.2
  Top Layer w10: H10.5@3700,4985 3757.84,4985 3916.97,5144.13 SW4.1@3918.78,5144.13 ; v1(4250,4995) 4275,5020 4411.4,5020 ; v3(4530.02,4754.25) 4456.66,4754.25 4411.55,4799.36 4411.55,5019.85 4411.4,5020 ; C12.2 4704.89,5054.89 4670,5020 4411.4,5020
  Bottom Layer w10: H10.5@3700,4985 3770.63,5055.63 R9.1 4076.91,4995 v1(4250,4995)
VCC_1V2: C16.2 FPC1.15 U11.5 | length 1561.5
  Top Layer w10: FPC1.15 7055.86,4514.14 7150,4420 v1(7150,4370)
  Bottom Layer w10: 6560,3950 6560,3970 6865,4275 7055,4275 v1(7150,4370)
  Bottom Layer w11.81: U11.5 6560,3756.18 6560,3950
  Bottom Layer w20: C16.2 U11.5
VCC_2V8: C20.1 FPC1.21 U10.2 | length 2572.3
  Top Layer w10: FPC1.21 7207.75,4632.25 v1(7210,4630)
  Bottom Layer w11.81: C20.1 6125.49,3380 6530,3380 6590,3440 6590,3960 6880,4250 7090,4250 7210,4370 v1(7210,4630)
  Bottom Layer w20: U10.2 6006.06,3499.43 C20.1
VCC_3V3: C5.2 C6.1 C7.2 C18.1 CN6.2 FPC1.14 R9.2 R10.2 R17.2 R18.2 R20.2 R21.2 R22.2 R23.2 R26.2 R27.2 R37.2 SW8.6 SW14.1 U4.5 U5.10 U7.4 U7.18 U7.20 U12.2 U14.2 U14.4 | length 14765.4
  Top Layer w10: v1(3975,4140) 4085,4140 4370,4425 v1(4370,4460) ; v1(6885,4545) 6900,4545 6950.55,4494.45 FPC1.14
  Top Layer w11.81: v1(4020,5125) 3965,5070 3965,4869.3 4048.67,4785.63 R21.2 ; v1(4995,4925) 5195,4925 5240,4880 5300,4880 5330,4850 5330,4805 5375,4760 5465,4760 5510,4805 v1(5510,4850) 5510,4895 5529.98,4914.98 ; R18.2 5545.34,5195 5529.98,5179.64 5529.98,4914.98 ; v1(5695,4945) 5560,4945 5529.98,4914.98 ; v1(5790,5195) 5790,5190 5975,5005 6170,5005 6193.59,5028.59 v1(6193.59,5066.31) ; v1(6455,4905) 6530,4830 6530,4779.33 6530,4735 6565,4700 6795,4700 v1(6825,4730)
  Top Layer w15.75: v1(3535,5200) 3990,5200 4020,5170 v1(4020,5125)
  Top Layer w20: v6(4952.69,3625) v1(5196.69,3625)
  Bottom Layer w10: 3345,4140.98 3974.02,4140.98 v1(3975,4140) ; v1(4020,5125) 4093.95,5125 4095.02,5123.93 ; 4278.52,5030 4278.78,5029.74 ; v1(4370,4460) 4373.27,4463.27 U7.4 ; v1@4990,4925 v1(4995,4925) ; v1(5510,4850) 5585,4850 5631.93,4803.07 U5.10
  Bottom Layer w11.81: R9.2 4120.65,5030 4278.52,5030 ; U7.18 4278.78,5029.74 4320.53,5029.74 4341.77,5008.5 U7.20 ; U4.5 v1(5695,4945) 5790,5040 v1(5790,5195) ; v1(6193.59,5066.31) 6293.69,5066.31 v1(6455,4905) ; R27.2 6775.32,4505.32 6825,4555 6825,4565 ; v1(6825,4730) R26.2@6825,4610.57 ; R26.2 R26.2@6825,4610.57 ; v1(6885,4545) 6845,4545 6825,4565 ; 6825,4565 R26.2@6825,4610.57
  Bottom Layer w15.75: R9.2 4095.02,5123.93 4095.02,5175.02 4157,5237 4808,5237
  Bottom Layer w20: 4808,5237 4910,5135 4910,5005 v1@4990,4925 ; v1(5196.69,3625) 5366,3625 C18.1
  Bottom Layer w39.37: v1(3535,5200) 3535,4930 3484.49,4879.48 CN6.2 3345,4804.48 3345,4140.98 3345,3750 3417.56,3677.44 C7.2 C5.2 3897.44,3600 4080,3600 4160,3520 4160,3360 4295,3225 4957.46,3225 ; v6(4952.69,3625) 4952.69,3356.71 ; R37.2 4952.81,3356.83 4952.69,3356.71 ; v1(6720,3805) 6855,3670 R23.2 7020,3668.75 7020,3480 6765,3225 4957.46,3225 ; 4952.69,3356.71 4952.69,3229.77 4957.46,3225
XTAL1: C3.2 U7.7 X1.1 | length 345.3
  Bottom Layer w20: U7.7 4278.78,4470.52 X1.1 4385,4364.3 C3.2
XTAL2: C4.2 U7.8 X1.2 | length 357.2
  Bottom Layer w20: X1.2 4093.54,4564.92 C4.2 4241.19,4604.09 U7.8 U7.8@4247.28,4593.74
"": CN6.9 FPC1.1 FPC1.2 FPC1.24 H6.2 H6.4 H6.6 H6.8 SW2.1 SW5.7 SW5.8 SW5.9 SW5.10 SW8.3 SW14.4 SW14.5 SW14.6 SW14.7 SW15.3 SW15.4 SW15.5 SW15.6 SW15.7 U7.23 U11.4 U12.17 U12.18 U12.19 U12.20 U12.21 U12.22 U12.27 U12.28 U12.32 U13.3 U13.5 USB1.4 USB1.6 USB1.7

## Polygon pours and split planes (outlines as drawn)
VCC_3V3 on Top Layer (solid, remove dead copper, pour order 0): 3210,3000 7325,3000 7325,5375 3210,5375
GND on Bottom Layer (solid, remove dead copper, pour order 1): 3000,3050 7440,3050 7440,5325 3000,5325

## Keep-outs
Board Outline Layer:
  lines w10 net "": 3315,3213.07 ccw(c3433.11,3213.07) 3433.11,3094.96 7133.9,3094.96 ccw(c7133.9,3213.07) 7252.01,3213.07 7252.01,5161.89 ccw(c7133.9,5161.89) 7133.9,5280 3433.11,5280 ccw(c3433.11,5161.89) 3315,5161.89 3315,3213.07

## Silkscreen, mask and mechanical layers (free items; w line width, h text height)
Top Silkscreen Layer:
  text "328PB_RST" at 3624.81,5229.99 h29.2
  text "LCD_EN" at 5858.66,5224.99 h29.2
  text "ESP_DL" at 4888.66,5219.99 h29.2
  text "→" at 6119.49,5204.69 h133.8
  text "→" at 4774.49,5199.69 h133.8
  text "D8" at 6410.74,5198.95 h29.2 r60
  text "CS" at 6510.74,5193.95 h29.2 r60
  text "DC" at 6610.74,5193.95 h29.2 r60
  text "RES" at 6710.1,5182.84 h29.2 r60
  text "3V3" at 6995.1,5182.84 h29.2 r60
  text "GND" at 7090.1,5182.84 h29.2 r60
  text "IO13" at 6799.46,5181.72 h29.2 r60
  text "IO14" at 6904.46,5176.72 h29.2 r60
  text "HUD" at 3360.64,5102.48 h51.1
  text "RST" at 3757.51,4969.99 h29.2
  text "DL_SL" at 5105.01,4964.94 h29.2 r90
  text "TX" at 5538.79,4954.99 h29.2
  text "RX" at 5668.79,4954.99 h29.2
  text "SCL" at 4410.1,4942.84 h29.2 r60
  text "SDA" at 4310.1,4937.84 h29.2 r60
  text "VCC" at 4210.1,4932.84 h29.2 r60
  text "GND" at 4515.1,4932.84 h29.2 r60
  text "PE3" at 4632.51,4892.66 h29.2 r90
  text "D13" at 3757.51,4869.99 h29.2
  text "328_DL" at 4768.66,4844.99 h29.2
  text "←" at 4949.49,4824.69 h133.8
  text "PE2" at 4635.01,4787.51 h29.2 r90
  text "D12" at 3757.51,4769.99 h29.2
  text "PE1" at 4805.01,4692.51 h29.2 r90
  text "D11" at 3757.51,4669.99 h29.2
  text "PE0" at 4805.01,4582.51 h29.2 r90
  text "D10" at 3757.51,4569.99 h29.2
  text "D2" at 4338.79,4534.99 h29.2
  text "SCL" at 4557.51,4519.99 h29.2
  text "GND" at 4657.51,4519.99 h29.2
  text "VCC" at 4752.51,4519.99 h29.2
  text "SDA" at 4457.51,4484.99 h29.2
  text "BATT_EN" at 3687.99,4425.73 h45.99
  text "←" at 3569.49,4414.69 h133.8
  text "EN_RST" at 6941.68,3728.11 h38.33
  text "BATT" at 3331.08,3708.6 h68.99
  text "IO0_RST" at 6930,3403.11 h38.33
  text "GND" at 6659.11,3248.6 h68.99
Bottom Silkscreen Layer:
  text "GND" at 3567.51,4959.99 h29.2
  text "VCC" at 3567.51,4864.99 h29.2
  text "SCL" at 3562.51,4764.99 h29.2
  text "SDA" at 3562.51,4669.99 h29.2
  text "RES" at 3562.51,4569.99 h29.2
  text "ESP_LED" at 6072.38,4504.99 h29.2
  text "DC" at 3548.79,4469.99 h29.2
  text "CS1" at 3557.51,4374.99 h29.2
  text "BLK" at 3557.51,4274.99 h29.2
  text "MFT中控板_V3" at 4276.79,4245.57 h111.5
  text "→" at 6995.51,4200.31 h133.8 r180
  text "FSO" at 3557.51,4174.99 h29.2
  text "IO0_DL_SL" at 6984.81,4149.99 h29.2
  text "Kevin_Wuu" at 4276.79,4120.57 h111.5
  text "CS2" at 3557.51,4079.99 h29.2
  text "2023/8/21" at 4271.79,3995.57 h111.5
  text "PWR" at 5455.64,3242.48 h51.1
Mechanical Layer:
  circle w1 net "": c7090,3255 r86.61
  circle w1 net "": c3475,3250 r86.61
